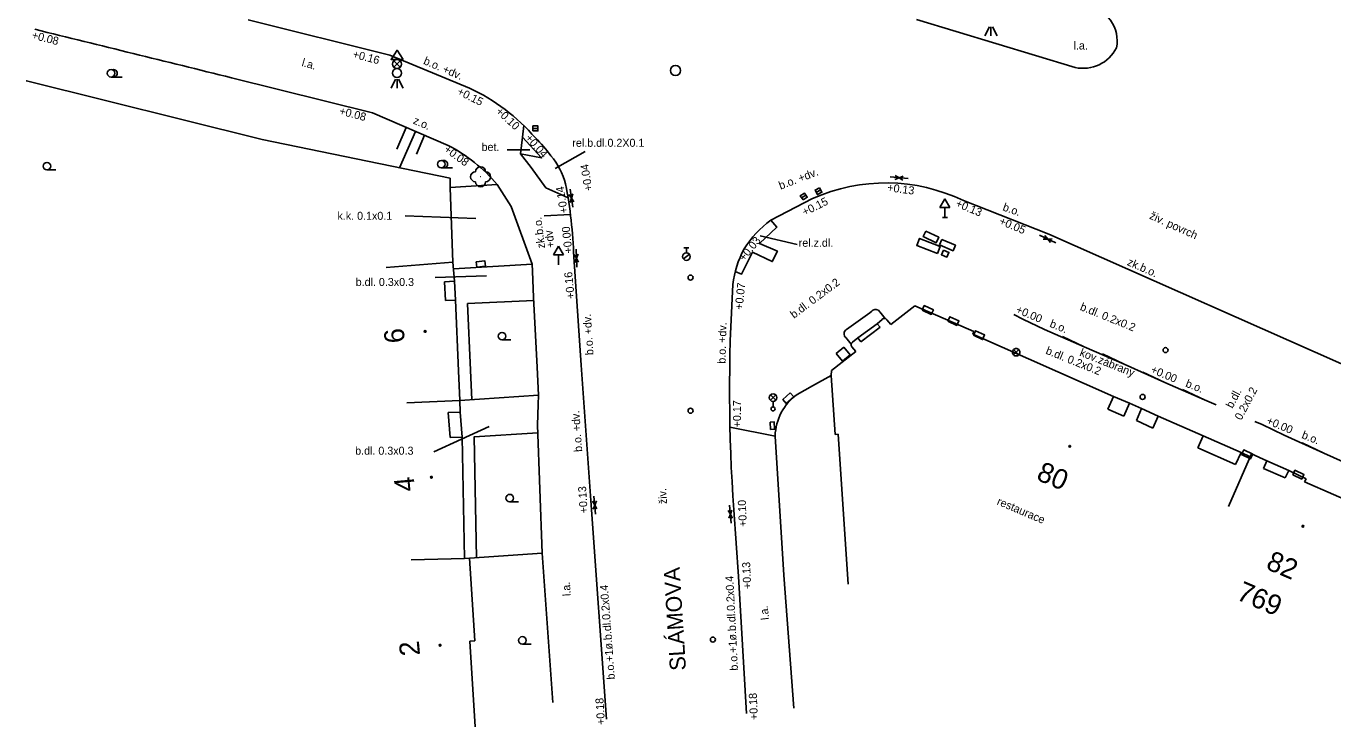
# Model space of a CAD drawing. Extents: x -596069 to -595683, y -1161832 to -1161593.
# Drawn here: x -596068.8 to -596003.5, y -1161675.6 to -1161640.6 of the extents above; entities that cross this region are included whole.
import ezdxf

# ---------------------------------------------------------------- set-up
doc = ezdxf.new("R2010")
doc.units = 0
for name, color, linetype in [('Vrstva 10', 7, 'Continuous'), ('Vrstva 12', 7, 'Continuous'), ('Vrstva 14', 7, 'Continuous'), ('Vrstva 15', 7, 'Continuous'), ('Vrstva 17', 7, 'Continuous'), ('Vrstva 19', 7, 'Continuous'), ('Vrstva 2', 7, 'Continuous'), ('Vrstva 23', 7, 'Continuous'), ('Vrstva 24', 7, 'Continuous'), ('Vrstva 25', 7, 'Continuous'), ('Vrstva 26', 7, 'Continuous'), ('Vrstva 28', 7, 'Continuous'), ('Vrstva 29', 7, 'Continuous'), ('Vrstva 34', 7, 'Continuous'), ('Vrstva 4', 7, 'Continuous'), ('Vrstva 42', 7, 'Continuous'), ('Vrstva 43', 7, 'Continuous'), ('Vrstva 44', 7, 'Continuous'), ('Vrstva 49', 7, 'Continuous'), ('Vrstva 5', 7, 'Continuous'), ('Vrstva 50', 7, 'Continuous'), ('Vrstva 7', 7, 'Continuous'), ('Vrstva 9', 7, 'Continuous')]:
    doc.layers.add(name, color=color, linetype=linetype)

msp = doc.modelspace()

# ---------------------------------------------------------------- linework, layer by layer
at = {"layer": 'Vrstva 10'}
for p, q in [((-596029.496, -1161658.607), (-596030.263, -1161659.03)), ((-596031.366, -1161661.115), (-596030.933, -1161668.069)), ((-596030.933, -1161668.069), (-596030.435, -1161674.71))]:
    msp.add_line(p, q, dxfattribs=at)
for points in [[(-596057.002, -1161646.306), (-596068.789, -1161643.375), (-596068.8, -1161643.373)], [(-596047.605, -1161648.236), (-596057.002, -1161646.306)], [(-596043.499, -1161652.875), (-596043.514, -1161652.53), (-596047.441, -1161652.761)], [(-596043.268, -1161657.676), (-596043.439, -1161654.194)], [(-596043.199, -1161659.074), (-596043.268, -1161657.676)], [(-596043.217, -1161659.531), (-596043.199, -1161659.074), (-596047.123, -1161659.336)], [(-596042.485, -1161674.429), (-596043.006, -1161666.965), (-596043.239, -1161660.567)]]:
    msp.add_lwpolyline(points, dxfattribs=at)
msp.add_arc((-596028.708, -1161661.187), 2.659, 125.78524, 178.45558, dxfattribs=at)
at = {"layer": 'Vrstva 12'}
for points in [[(-596047.616, -1161648.699), (-596047.605, -1161648.236)], [(-596047.467, -1161652.434), (-596047.488, -1161651.982)]]:
    msp.add_lwpolyline(points, dxfattribs=at)
at = {"layer": 'Vrstva 14'}
for p, q in [((-596064.558, -1161643.179), (-596063.996, -1161643.179)), ((-596067.759, -1161647.817), (-596067.321, -1161647.817)), ((-596048.051, -1161647.719), (-596047.489, -1161647.719)), ((-596045.013, -1161656.312), (-596044.575, -1161656.312)), ((-596044.63, -1161664.403), (-596044.192, -1161664.403)), ((-596044, -1161671.508), (-596043.562, -1161671.508))]:
    msp.add_line(p, q, dxfattribs=at)
for centre, radius in [((-596064.558, -1161642.991), 0.188), ((-596067.759, -1161647.629), 0.188), ((-596048.051, -1161647.531), 0.188), ((-596046.09, -1161648.16), 0.00025), ((-596045.013, -1161656.124), 0.188), ((-596044.63, -1161664.215), 0.188), ((-596044, -1161671.32), 0.188)]:
    msp.add_circle(centre, radius, dxfattribs=at)
for centre, radius, start, end in [((-596064.433, -1161642.991), 0.188, 249.49437, 109.04743), ((-596047.926, -1161647.531), 0.188, 249.49437, 109.04743), ((-596046.09, -1161647.91), 0.25, 0, 179.99999), ((-596046.34, -1161648.16), 0.25, 89.99999, 269.99999), ((-596046.09, -1161648.41), 0.25, 179.99999, 359.99999), ((-596045.84, -1161648.16), 0.25, 270, 89.99999)]:
    msp.add_arc(centre, radius, start, end, dxfattribs=at)
at = {"layer": 'Vrstva 15'}
for centre in [(-596048.858, -1161655.886), (-596016.645, -1161661.626), (-596048.545, -1161663.17), (-596004.99, -1161665.62), (-596048.113, -1161671.563)]:
    msp.add_circle(centre, 0.0438, dxfattribs=at)
at = {"layer": 'Vrstva 17'}
msp.add_lwpolyline([(-596047.616, -1161648.699), (-596045.26, -1161648.55)], dxfattribs=at)
at = {"layer": 'Vrstva 19'}
for p, q in [((-596022.886, -1161649.263), (-596023.136, -1161649.696)), ((-596023.136, -1161649.696), (-596022.636, -1161649.696)), ((-596022.886, -1161649.263), (-596022.636, -1161649.696)), ((-596022.886, -1161650.196), (-596022.886, -1161649.696)), ((-596023.011, -1161650.196), (-596022.761, -1161650.196)), ((-596042.197, -1161651.626), (-596042.447, -1161652.059)), ((-596042.197, -1161651.626), (-596041.947, -1161652.059)), ((-596042.447, -1161652.059), (-596041.947, -1161652.059)), ((-596042.197, -1161652.559), (-596042.197, -1161652.059))]:
    msp.add_line(p, q, dxfattribs=at)
at = {"layer": 'Vrstva 2'}
for p, q in [((-596019.455, -1161656.795), (-596019.323, -1161656.927)), ((-596019.455, -1161657.059), (-596019.323, -1161656.927)), ((-596019.323, -1161656.927), (-596019.455, -1161657.059)), ((-596019.191, -1161656.795), (-596019.323, -1161656.927)), ((-596019.191, -1161657.059), (-596019.323, -1161656.927)), ((-596019.323, -1161656.927), (-596019.191, -1161657.059)), ((-596019.323, -1161656.927), (-596019.191, -1161657.059))]:
    msp.add_line(p, q, dxfattribs=at)
for start, end in [(134.99216, 225.00785), (44.99215, 135.00784), (314.99214, 45.00783), (224.99216, 315.00785)]:
    msp.add_arc((-596019.323, -1161656.927), 0.187, start, end, dxfattribs=at)
at = {"layer": 'Vrstva 23'}
for p, q in [((-596027.928, -1161656.669), (-596028.318, -1161656.981)), ((-596028.318, -1161656.981), (-596028.005, -1161657.372)), ((-596027.615, -1161657.059), (-596027.928, -1161656.669)), ((-596028.005, -1161657.372), (-596027.615, -1161657.059))]:
    msp.add_line(p, q, dxfattribs=at)
for centre in [(-596035.596, -1161659.85), (-596034.478, -1161671.282)]:
    msp.add_circle(centre, 0.125, dxfattribs=at)
at = {"layer": 'Vrstva 24'}
for p, q in [((-596035.927, -1161651.709), (-596035.677, -1161651.709)), ((-596035.802, -1161651.959), (-596035.802, -1161651.709)), ((-596035.949, -1161652.263), (-596035.654, -1161652.031))]:
    msp.add_line(p, q, dxfattribs=at)
for centre, radius in [((-596035.802, -1161652.147), 0.188), ((-596035.595, -1161653.197), 0.125)]:
    msp.add_circle(centre, radius, dxfattribs=at)
at = {"layer": 'Vrstva 25'}
for p, q in [((-596043.472, -1161645.748), (-596043.222, -1161645.748)), ((-596030.042, -1161649.213), (-596029.834, -1161649.075)), ((-596029.088, -1161648.819), (-596029.308, -1161648.937))]:
    msp.add_line(p, q, dxfattribs=at)
for points in [[(-596043.472, -1161645.873), (-596043.222, -1161645.873), (-596043.222, -1161645.623), (-596043.472, -1161645.623)], [(-596029.974, -1161649.317), (-596029.765, -1161649.18), (-596029.902, -1161648.971), (-596030.111, -1161649.108)], [(-596029.146, -1161648.709), (-596029.367, -1161648.826), (-596029.25, -1161649.047), (-596029.029, -1161648.93)]]:
    msp.add_lwpolyline(points, close=True, dxfattribs=at)
msp.add_circle((-596036.347, -1161642.849), 0.25, dxfattribs=at)
at = {"layer": 'Vrstva 26'}
for centre in [(-596011.855, -1161656.822), (-596013.003, -1161659.159)]:
    msp.add_circle(centre, 0.125, dxfattribs=at)
at = {"layer": 'Vrstva 28'}
for p, q in [((-596049.804, -1161645.692), (-596050.27, -1161646.774)), ((-596049.345, -1161645.89), (-596050.132, -1161647.717)), ((-596048.886, -1161646.088), (-596049.294, -1161647.035))]:
    msp.add_line(p, q, dxfattribs=at)
at = {"layer": 'Vrstva 29'}
for p, q in [((-596031.602, -1161659.326), (-596031.338, -1161659.062)), ((-596031.334, -1161659.325), (-596031.598, -1161659.06)), ((-596031.47, -1161659.657), (-596031.47, -1161659.382))]:
    msp.add_line(p, q, dxfattribs=at)
for points in [[(-596023.84, -1161650.88), (-596023.19, -1161651.18), (-596023.316, -1161651.452), (-596023.966, -1161651.152)], [(-596023.84, -1161650.88), (-596023.19, -1161651.18), (-596023.316, -1161651.452), (-596023.966, -1161651.152)], [(-596023.258, -1161651.99), (-596024.288, -1161651.592), (-596024.151, -1161651.238), (-596023.121, -1161651.636)], [(-596023.04, -1161651.29), (-596022.36, -1161651.58), (-596022.478, -1161651.856), (-596023.158, -1161651.566)], [(-596023.04, -1161651.29), (-596022.36, -1161651.58), (-596022.478, -1161651.856), (-596023.158, -1161651.566)], [(-596046.31, -1161652.41), (-596045.87, -1161652.36), (-596045.841, -1161652.618), (-596046.281, -1161652.668)], [(-596022.956, -1161651.822), (-596022.681, -1161651.94), (-596022.779, -1161652.17), (-596023.054, -1161652.052)], [(-596024.018, -1161654.824), (-596023.565, -1161655.035), (-596023.46, -1161654.808), (-596023.913, -1161654.597)], [(-596022.74, -1161655.377), (-596022.287, -1161655.588), (-596022.182, -1161655.361), (-596022.635, -1161655.15)], [(-596021.454, -1161656.08), (-596021.001, -1161656.291), (-596020.896, -1161656.064), (-596021.349, -1161655.853)], [(-596030.608, -1161658.961), (-596030.979, -1161659.295), (-596030.812, -1161659.481), (-596030.441, -1161659.147)], [(-596031.613, -1161660.422), (-596031.593, -1161660.786), (-596031.393, -1161660.775), (-596031.413, -1161660.411)], [(-596005.499, -1161663.053), (-596005.046, -1161663.264), (-596004.941, -1161663.037), (-596005.394, -1161662.826)]]:
    msp.add_lwpolyline(points, close=True, dxfattribs=at)
for centre, radius in [((-596031.47, -1161659.194), 0.188), ((-596031.47, -1161659.757), 0.1)]:
    msp.add_circle(centre, radius, dxfattribs=at)
at = {"layer": 'Vrstva 34'}
msp.add_lwpolyline([(-596008.055, -1161662.035), (-596007.602, -1161662.246), (-596007.497, -1161662.019), (-596007.95, -1161661.808)], close=True, dxfattribs=at)
at = {"layer": 'Vrstva 4'}
for p, q in [((-596047.393, -1161653.377), (-596047.891, -1161653.416)), ((-596047.348, -1161654.326), (-596047.847, -1161654.348)), ((-596026.015, -1161655.283), (-596026.268, -1161655.501)), ((-596026.123, -1161655.669), (-596026.268, -1161655.501)), ((-596027.504, -1161656.421), (-596027.242, -1161656.212)), ((-596027.086, -1161656.408), (-596027.242, -1161656.212)), ((-596021.486, -1161656.016), (-596014.463, -1161659.135)), ((-596028.55, -1161657.845), (-596027.338, -1161656.895)), ((-596028.563, -1161658.091), (-596028.55, -1161657.845)), ((-596014.463, -1161659.135), (-596014.747, -1161659.775)), ((-596013.658, -1161659.475), (-596013.935, -1161660.118)), ((-596013.055, -1161659.735), (-596013.312, -1161660.332)), ((-596009.982, -1161661.104), (-596010.242, -1161661.7)), ((-596008.07, -1161661.943), (-596008.353, -1161662.528)), ((-596007.632, -1161662.155), (-596008.07, -1161661.943)), ((-596000.293, -1161665.422), (-596004.908, -1161663.397))]:
    msp.add_line(p, q, dxfattribs=at)
for points in [[(-596047.467, -1161652.434), (-596050.815, -1161652.697)], [(-596047.393, -1161653.377), (-596047.467, -1161652.434)], [(-596047.393, -1161653.377), (-596047.348, -1161654.326)], [(-596047.189, -1161657.858), (-596047.348, -1161654.326)], [(-596026.642, -1161654.953), (-596027.804, -1161655.79)], [(-596026.642, -1161654.953), (-596026.535, -1161654.868)], [(-596026.129, -1161654.915), (-596025.864, -1161655.238)], [(-596024.39, -1161654.61), (-596025.579, -1161655.534)], [(-596024.39, -1161654.61), (-596021.43, -1161655.887)], [(-596027.242, -1161656.212), (-596026.268, -1161655.501)], [(-596025.579, -1161655.534), (-596025.78, -1161655.3)], [(-596027.837, -1161656.197), (-596027.572, -1161656.52)], [(-596021.43, -1161655.887), (-596021.486, -1161656.016)], [(-596027.338, -1161656.895), (-596027.531, -1161656.653)], [(-596047.123, -1161659.336), (-596047.189, -1161657.858)], [(-596028.563, -1161658.091), (-596028.362, -1161661.031)], [(-596047.123, -1161659.336), (-596049.776, -1161659.455)], [(-596047.104, -1161659.92), (-596047.123, -1161659.336)], [(-596014.463, -1161659.135), (-596013.658, -1161659.475)], [(-596013.055, -1161659.735), (-596013.658, -1161659.475)], [(-596047.104, -1161659.92), (-596047.704, -1161659.94)], [(-596047.104, -1161659.92), (-596047.016, -1161661.171)], [(-596013.055, -1161659.735), (-596012.227, -1161660.125)], [(-596012.227, -1161660.125), (-596012.487, -1161660.721)], [(-596009.982, -1161661.104), (-596012.227, -1161660.125)], [(-596047.016, -1161661.171), (-596047.616, -1161661.183)], [(-596046.892, -1161667.236), (-596047.016, -1161661.171)], [(-596028.362, -1161661.031), (-596028.212, -1161661.021)], [(-596028.212, -1161661.021), (-596027.712, -1161668.515)], [(-596009.982, -1161661.104), (-596008.07, -1161661.943)], [(-596007.568, -1161662.008), (-596008.714, -1161664.64)], [(-596006.794, -1161662.345), (-596007.568, -1161662.008)], [(-596006.794, -1161662.345), (-596006.962, -1161662.73)], [(-596006.794, -1161662.345), (-596005.686, -1161662.83)], [(-596005.686, -1161662.83), (-596005.87, -1161663.208)], [(-596004.834, -1161663.244), (-596005.686, -1161662.83)], [(-596004.834, -1161663.244), (-596004.908, -1161663.397)], [(-596046.892, -1161667.236), (-596049.551, -1161667.29)], [(-596046.643, -1161667.22), (-596046.892, -1161667.236)], [(-596046.377, -1161671.346), (-596046.643, -1161667.22)], [(-596046.377, -1161671.346), (-596046.626, -1161671.362)], [(-596046.626, -1161671.362), (-596046.351, -1161675.642)]]:
    msp.add_lwpolyline(points, dxfattribs=at)
for centre, radius, start, end in [((-596026.349, -1161655.043), 0.255, 30.08931, 136.64801), ((-596025.904, -1161655.386), 0.151, 35.19991, 136.56088), ((-596027.669, -1161656.006), 0.255, 122.08519, 228.64388), ((-596027.422, -1161656.548), 0.151, 122.68134, 224.0423)]:
    msp.add_arc(centre, radius, start, end, dxfattribs=at)
at = {"layer": 'Vrstva 44'}
for p, q in [((-596020.653, -1161640.664), (-596020.879, -1161641.116)), ((-596020.579, -1161640.666), (-596020.579, -1161641.116)), ((-596020.504, -1161640.664), (-596020.279, -1161641.116)), ((-596050.105, -1161642.367), (-596050.425, -1161642.687)), ((-596050.425, -1161642.367), (-596050.105, -1161642.687)), ((-596050.34, -1161643.277), (-596050.565, -1161643.727)), ((-596050.265, -1161643.277), (-596050.265, -1161643.727)), ((-596050.19, -1161643.277), (-596049.965, -1161643.727)), ((-596017.905, -1161655.785), (-596018.992, -1161655.268)), ((-596015.916, -1161656.65), (-596017.003, -1161656.133)), ((-596013.916, -1161657.524), (-596015.003, -1161657.007)), ((-596011.899, -1161658.436), (-596012.986, -1161657.919)), ((-596009.916, -1161659.309), (-596011.003, -1161658.792)), ((-596005.933, -1161661.061), (-596007.02, -1161660.544)), ((-596003.946, -1161661.974), (-596005.033, -1161661.457))]:
    msp.add_line(p, q, dxfattribs=at)
msp.add_lwpolyline([(-596049.961, -1161642.296), (-596050.563, -1161642.296), (-596050.264, -1161641.839)], close=True, dxfattribs=at)
for centre, radius in [((-596050.265, -1161642.527), 0.226), ((-596050.265, -1161642.977), 0.224)]:
    msp.add_circle(centre, radius, dxfattribs=at)
at = {"layer": 'Vrstva 49'}
for p, q in [((-596044.76, -1161646.819), (-596043.622, -1161646.819)), ((-596042.365, -1161647.742), (-596040.854, -1161646.898)), ((-596024.725, -1161648.25), (-596025.623, -1161648.17)), ((-596025.174, -1161648.21), (-596025.383, -1161648.291)), ((-596025.174, -1161648.21), (-596025.365, -1161648.095)), ((-596025.174, -1161648.21), (-596024.967, -1161648.127)), ((-596025.174, -1161648.21), (-596024.986, -1161648.327)), ((-596041.551, -1161649.228), (-596041.68, -1161649.046)), ((-596041.617, -1161648.782), (-596041.485, -1161649.674)), ((-596041.551, -1161649.228), (-596041.482, -1161649.018)), ((-596041.551, -1161649.228), (-596041.618, -1161649.441)), ((-596041.551, -1161649.228), (-596041.423, -1161649.412)), ((-596046.332, -1161650.25), (-596049.862, -1161650.112)), ((-596042.916, -1161650.116), (-596041.595, -1161650.037)), ((-596032.112, -1161651.107), (-596030.267, -1161651.539)), ((-596017.332, -1161651.457), (-596018.152, -1161651.083)), ((-596017.742, -1161651.27), (-596017.884, -1161651.098)), ((-596017.742, -1161651.27), (-596017.966, -1161651.277)), ((-596017.742, -1161651.27), (-596017.519, -1161651.261)), ((-596017.742, -1161651.27), (-596017.604, -1161651.443)), ((-596041.296, -1161652.232), (-596041.406, -1161652.038)), ((-596041.296, -1161652.232), (-596041.384, -1161652.437)), ((-596041.318, -1161651.782), (-596041.274, -1161652.682)), ((-596041.296, -1161652.232), (-596041.206, -1161652.03)), ((-596041.296, -1161652.232), (-596041.187, -1161652.428)), ((-596048.358, -1161653.187), (-596045.794, -1161653.108)), ((-596048.419, -1161661.904), (-596045.657, -1161660.64)), ((-596040.423, -1161664.114), (-596040.349, -1161665.012)), ((-596040.386, -1161664.563), (-596040.502, -1161664.373)), ((-596040.386, -1161664.563), (-596040.467, -1161664.771)), ((-596040.386, -1161664.563), (-596040.303, -1161664.358)), ((-596040.386, -1161664.563), (-596040.271, -1161664.756)), ((-596033.606, -1161665.016), (-596033.722, -1161664.826)), ((-596033.643, -1161664.567), (-596033.569, -1161665.465)), ((-596033.606, -1161665.016), (-596033.523, -1161664.811)), ((-596033.606, -1161665.016), (-596033.687, -1161665.224)), ((-596033.606, -1161665.016), (-596033.491, -1161665.209))]:
    msp.add_line(p, q, dxfattribs=at)
at = {"layer": 'Vrstva 5'}
for p, q in [((-596047.488, -1161651.982), (-596047.616, -1161648.699)), ((-596043.439, -1161654.194), (-596043.499, -1161652.875)), ((-596047.891, -1161653.416), (-596047.847, -1161654.348)), ((-596026.123, -1161655.669), (-596027.086, -1161656.408)), ((-596029.496, -1161658.607), (-596028.563, -1161658.091)), ((-596043.239, -1161660.567), (-596043.217, -1161659.531)), ((-596047.704, -1161659.94), (-596047.616, -1161661.183)), ((-596013.935, -1161660.118), (-596014.747, -1161659.775)), ((-596012.487, -1161660.721), (-596013.312, -1161660.332)), ((-596008.353, -1161662.528), (-596010.242, -1161661.7)), ((-596006.962, -1161662.73), (-596005.873, -1161663.207))]:
    msp.add_line(p, q, dxfattribs=at)
at = {"layer": 'Vrstva 7'}
for p, q in [((-596024.308, -1161640.295), (-596016.373, -1161642.7)), ((-596009.916, -1161659.309), (-596009.329, -1161659.557)), ((-596007.02, -1161660.544), (-596007.387, -1161660.383)), ((-596007.02, -1161660.544), (-596005.933, -1161661.061)), ((-596005.933, -1161661.061), (-596003.946, -1161661.974)), ((-596003.946, -1161661.974), (-596001.954, -1161662.87))]:
    msp.add_line(p, q, dxfattribs=at)
for points in [[(-596050.625, -1161642.091), (-596057.7, -1161640.323)], [(-596046.644, -1161643.734), (-596050.625, -1161642.091)], [(-596058.536, -1161643.214), (-596051.492, -1161644.965)], [(-596047.709, -1161646.595), (-596051.492, -1161644.965)], [(-596043.56, -1161647.697), (-596044.099, -1161647.015), (-596043.04, -1161647.222), (-596043.996, -1161646.177), (-596043.928, -1161645.603)], [(-596044.099, -1161647.015), (-596043.996, -1161646.177)], [(-596042.084, -1161649.038), (-596042.82, -1161648.705), (-596043.56, -1161647.697)], [(-596043.514, -1161652.53), (-596044.562, -1161649.642), (-596045.26, -1161648.55)], [(-596041.713, -1161649.219), (-596042.084, -1161649.038)], [(-596029.493, -1161649.245), (-596031.576, -1161650.332)], [(-595992.773, -1161662.939), (-595992.538, -1161662.463), (-595992.446, -1161662.231), (-596001.752, -1161658.08), (-596017.691, -1161651.031), (-596021.958, -1161649.351)], [(-596031.576, -1161650.332), (-596031.28, -1161650.673), (-596032.144, -1161651.5), (-596031.254, -1161651.877), (-596031.509, -1161652.396), (-596032.505, -1161651.931), (-596033.043, -1161653.018), (-596033.357, -1161652.887)], [(-596041.055, -1161657.573), (-596041.432, -1161652.163)], [(-596046.59, -1161657.83), (-596046.74, -1161654.496), (-596043.432, -1161654.338)], [(-596019.433, -1161655.034), (-596018.992, -1161655.268), (-596017.905, -1161655.785), (-596015.916, -1161656.65), (-596013.916, -1161657.524), (-596011.899, -1161658.436), (-596009.916, -1161659.309)], [(-596039.791, -1161675.262), (-596040.584, -1161664.339), (-596041.055, -1161657.573)], [(-596046.524, -1161659.309), (-596046.59, -1161657.83)], [(-596033.624, -1161660.675), (-596031.366, -1161661.115)], [(-596046.293, -1161667.195), (-596046.416, -1161661.159), (-596043.224, -1161660.946)], [(-596033.434, -1161664.796), (-596033.193, -1161668.136), (-596032.803, -1161674.972)]]:
    msp.add_lwpolyline(points, dxfattribs=at)
for centre, radius, start, end in [((-596016.039, -1161641.375), 1.766, 348.72779, 82.86771), ((-602650.419, -1188377.711), 27535.183, 76.1489556, 76.1700083), ((-596015.979, -1161640.862), 1.88, 257.90958, 332.84475), ((-596050.681, -1161652.508), 9.658, 40.62229, 65.2936), ((-596047.429, -1161650.552), 5.95, 35.35968, 46.72867), ((-596051.363, -1161653.683), 7.975, 40.06928, 62.73104), ((-596045.461, -1161649.521), 3.76, 15.46285, 39.88986), ((-596025.84, -1161657.408), 8.943, 64.27709, 114.11098), ((-596064.39, -1161652.869), 22.969, 1.76117, 10.91921), ((-596028.611, -1161654.457), 5.08, 125.71036, 148.02603), ((-596028.582, -1161654.105), 4.928, 151.6799, 173.46456), ((-595949.041, -1161658.84), 84.603, 176.41081, 184.03682)]:
    msp.add_arc(centre, radius, start, end, dxfattribs=at)
at = {"layer": 'Vrstva 9'}
msp.add_lwpolyline([(-596043.006, -1161666.965), (-596046.643, -1161667.22)], dxfattribs=at)

# ---------------------------------------------------------------- texts
at = {"layer": 'Vrstva 42'}
msp.add_text('SLÁMOVA', height=0.8, rotation=93.55605, dxfattribs=at).set_placement((-596035.82, -1161672.807))
at = {"layer": 'Vrstva 43'}
for s, rotation, p in [('6', 95, (-596049.87, -1161656.431)), ('80', 337, (-596018.363, -1161663.276)), ('4', 95, (-596049.365, -1161663.849)), ('82', 337, (-596006.891, -1161667.732)), ('769', 337, (-596008.366, -1161669.256)), ('2', 95, (-596049.11, -1161672.057))]:
    msp.add_text(s, height=1, rotation=rotation, dxfattribs=at).set_placement(p)
at = {"layer": 'Vrstva 49'}
for s, p in [('l.a.', (-596016.453, -1161641.802)), ('bet.', (-596046.039, -1161646.872)), ('rel.b.dl.0.2X0.1', (-596041.501, -1161646.662)), ('k.k. 0.1x0.1', (-596053.24, -1161650.309)), ('rel.z.dl.', (-596030.188, -1161651.657)), ('b.dl. 0.3x0.3', (-596052.329, -1161653.616)), ('b.dl. 0.3x0.3', (-596052.356, -1161662.046))]:
    msp.add_text(s, height=0.4, dxfattribs=at).set_placement(p)
for s, rotation, p in [('l.a.', 343.96588, (-596055.055, -1161642.62)), ('b.o. +dv.', 336.7068, (-596048.978, -1161642.514)), ('z.o.', 336.7068, (-596049.495, -1161645.488)), ('b.o. +dv.', 20.82995, (-596031.097, -1161648.805)), ('b.o.', 340.66679, (-596020.026, -1161649.833)), ('zk.b.o.', 96.93435, (-596042.862, -1161651.719)), ('živ. povrch', 335.61059, (-596012.695, -1161650.239)), ('+dv', 96.93435, (-596042.389, -1161651.685)), ('zk.b.o.', 336.35155, (-596013.807, -1161652.561)), ('b.dl. 0.2x0.2', 36.76704, (-596030.428, -1161655.258)), ('b.dl. 0.2x0.2', 338.02638, (-596016.161, -1161654.807)), ('b.o. +dv.', 93.59039, (-596040.445, -1161657.058)), ('b.o. +dv.', 88.50944, (-596033.849, -1161657.5)), ('b.o.', 338.31682, (-596017.679, -1161655.65)), ('b.dl. 0.2x0.2', 338.02638, (-596017.878, -1161656.994)), ('kov.zábrany', 338.31682, (-596016.179, -1161657.091)), ('b.o.', 338.31682, (-596010.891, -1161658.638)), ('b.dl.', 62.10216, (-596008.513, -1161659.76)), ('0.2x0.2', 62.10216, (-596008.073, -1161660.354)), ('b.o. +dv.', 94.13166, (-596041.007, -1161661.893)), ('b.o.', 338.31682, (-596005.085, -1161661.208)), ('živ.', 93.4647, (-596036.767, -1161664.503)), ('restaurace', 337, (-596020.315, -1161664.52)), ('l.a.', 93.70059, (-596041.578, -1161669.095)), ('b.o.+1ø.b.dl.0.2x0.4', 94.29762, (-596039.375, -1161673.263)), ('b.o.+1ø.b.dl.0.2x0.4', 92.84654, (-596033.224, -1161672.824)), ('l.a.', 96.45403, (-596031.661, -1161670.275))]:
    msp.add_text(s, height=0.4, rotation=rotation, dxfattribs=at).set_placement(p)
at = {"layer": 'Vrstva 50'}
for s, rotation, p in [('+0.08', 345.75362, (-596068.544, -1161641.255)), ('+0.16', 345.52971, (-596052.508, -1161642.205)), ('+0.15', 333.37681, (-596047.294, -1161644.024)), ('+0.08', 345.75362, (-596053.179, -1161645.046)), ('+0.10', 317.09722, (-596045.354, -1161644.936)), ('+0.04', 311.50852, (-596043.881, -1161646.241)), ('+0.08', 324.15324, (-596047.952, -1161646.867)), ('+0.04', 99.31668, (-596040.492, -1161648.837)), ('+0.14', 99.31668, (-596041.723, -1161649.954)), ('+0.13', 352.73795, (-596025.78, -1161648.882)), ('+0.15', 26.48195, (-596029.89, -1161650.124)), ('+0.13', 337.29655, (-596022.382, -1161649.634)), ('+0.05', 337.59902, (-596020.205, -1161650.52)), ('+0.00', 95.86547, (-596041.497, -1161651.97)), ('+0.03', 51.22664, (-596032.907, -1161652.408)), ('+0.16', 95.86547, (-596041.379, -1161654.237)), ('+0.07', 84.03167, (-596032.995, -1161654.82)), ('+0.00', 337.06303, (-596019.373, -1161654.94)), ('+0.00', 337.06303, (-596012.633, -1161657.935)), ('+0.17', 90, (-596033.074, -1161660.679)), ('+0.00', 337.06303, (-596006.847, -1161660.487)), ('+0.13', 93.69892, (-596040.733, -1161664.96)), ('+0.10', 92.52275, (-596032.778, -1161665.647)), ('+0.13', 92.52275, (-596032.561, -1161668.748)), ('+0.18', 92.52275, (-596032.227, -1161675.292)), ('+0.18', 93.69892, (-596039.868, -1161675.534))]:
    msp.add_text(s, height=0.4, rotation=rotation, dxfattribs=at).set_placement(p)

doc.saveas('drawing.dxf')
